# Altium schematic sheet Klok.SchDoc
size A4
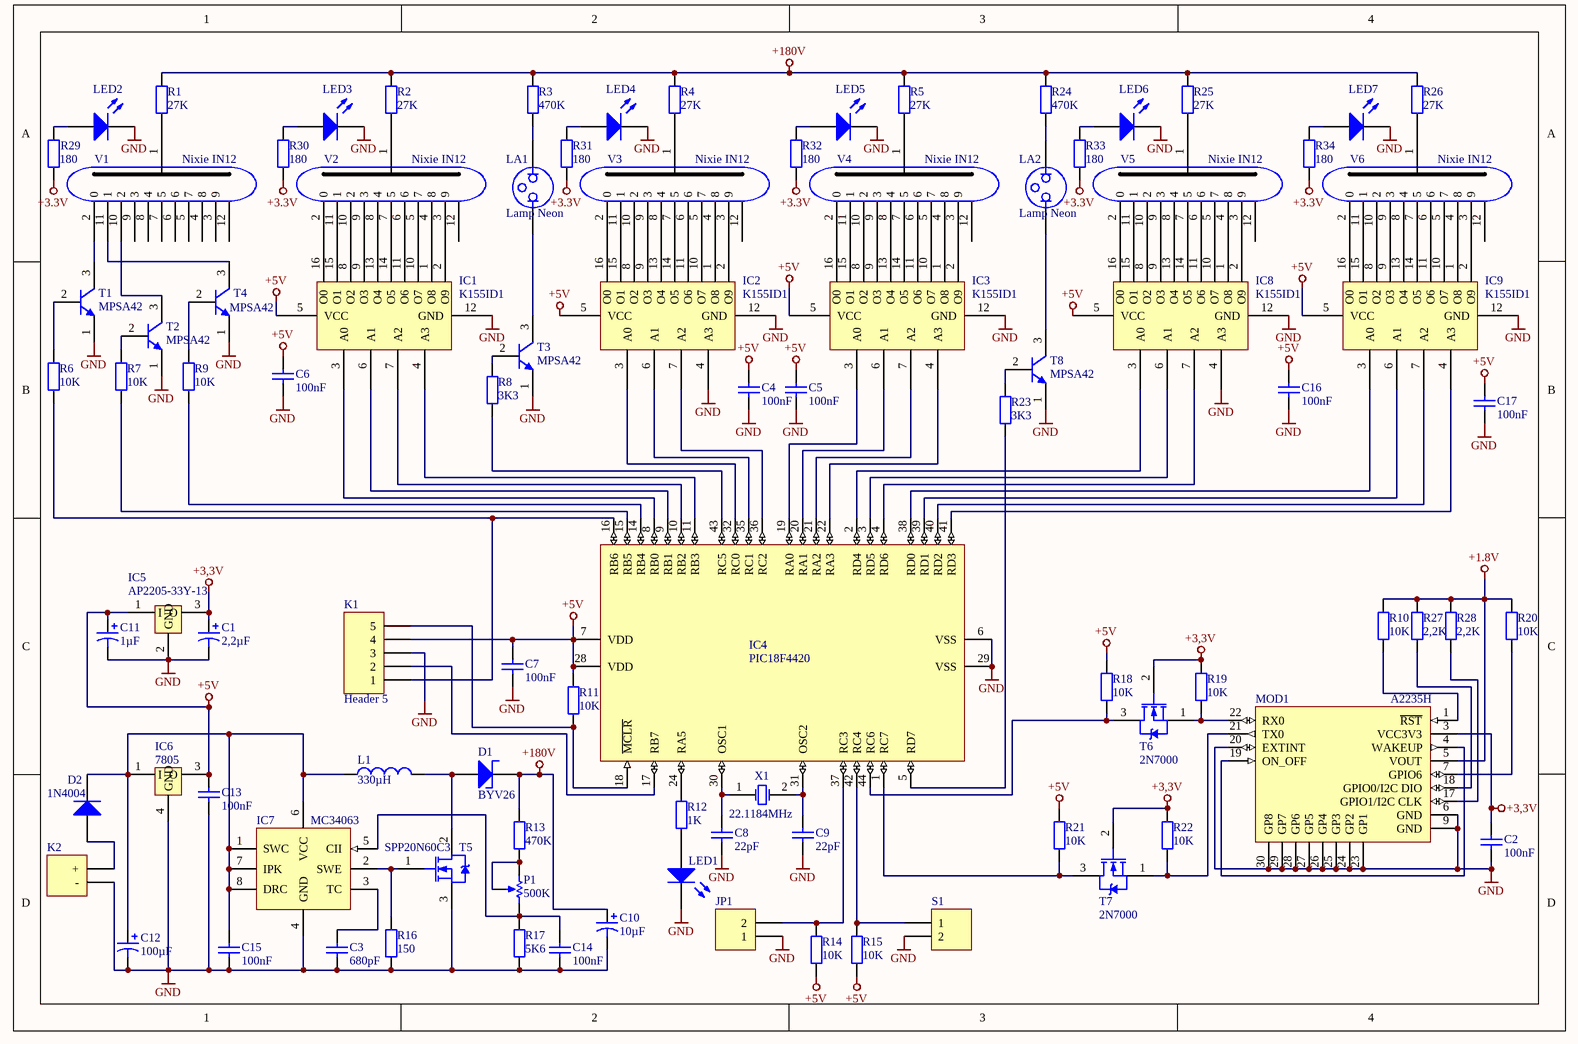
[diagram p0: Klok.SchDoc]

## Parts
C1  value 2,2µF  [ELCO2.2]  (hidden comment: Cap Pol1)
C2  value 100nF  [1206_Capacitor]  (hidden comment: Cap)
C3  value 680pF  [1206_Capacitor]  (hidden comment: Cap)
C4  value 100nF  [1206_Capacitor]  (hidden comment: Cap)
C5  value 100nF  [1206_Capacitor]  (hidden comment: Cap)
C6  value 100nF  [1206_Capacitor]  (hidden comment: Cap)
C7  value 100nF  [1206_Capacitor]  (hidden comment: Cap)
C8  value 22pF  [1206_Capacitor]  (hidden comment: Cap)
C9  value 22pF  [1206_Capacitor]  (hidden comment: Cap)
C10  value 10µF  [ELCO10]  (hidden comment: Cap Pol1)
C11  value 1µF  [ELCO100]  (hidden comment: Cap Pol1)
C12  value 100µF  [ELCO100]  (hidden comment: Cap Pol1)
C13  value 100nF  [1206_Capacitor]  (hidden comment: Cap)
C14  value 100nF  [1206_Capacitor]  (hidden comment: Cap)
C15  value 100nF  [1206_Capacitor]  (hidden comment: Cap)
C16  value 100nF  [1206_Capacitor]  (hidden comment: Cap)
C17  value 100nF  [1206_Capacitor]  (hidden comment: Cap)
D1  BYV26  [Through_Hole]
D2  1N4004  [DO-41]
IC1  K155ID1  [K155ID1]
IC2  K155ID1  [K155ID1]
IC3  K155ID1  [K155ID1]
IC4  PIC18F4420  [PIC18F4420]
IC5  AP2205-33Y-13  [AP2205-33Y-13]
IC6  7805  [7805]
IC7  MC34063  [MC34063]
IC8  K155ID1  [K155ID1]
IC9  K155ID1  [K155ID1]
JP1  Header 2  [HDR1X2]  (value not drawn)
K1  Header 5  [HDR1X5]
K2  Kroonsteen  [KROONSTEEN]  (value not drawn)
L1  value 330µH  [Inductor]  (hidden comment: Inductor)
LA1  Lamp Neon  [Neon_Lamp]
LA2  Lamp Neon  [Neon_Lamp]
LED1  LED0  [1206_LED]  (value not drawn)
LED2  LED0  [1206_LED]  (value not drawn)
LED3  LED0  [1206_LED]  (value not drawn)
LED4  LED0  [1206_LED]  (value not drawn)
LED5  LED0  [1206_LED]  (value not drawn)
LED6  LED0  [1206_LED]  (value not drawn)
LED7  LED0  [1206_LED]  (value not drawn)
MOD1  A2235H  [A2235H]
P1  value 500K  [Pot]  (hidden comment: RPot)
R1  value 27K  [1206_Resistor]  (hidden comment: Res2)
R2  value 27K  [1206_Resistor]  (hidden comment: Res2)
R3  value 470K  [1206_Resistor]  (hidden comment: Res2)
R4  value 27K  [1206_Resistor]  (hidden comment: Res2)
R5  value 27K  [1206_Resistor]  (hidden comment: Res2)
R6  value 10K  [1206_Resistor]  (hidden comment: Res2)
R7  value 10K  [1206_Resistor]  (hidden comment: Res2)
R8  value 3K3  [1206_Resistor]  (hidden comment: Res2)
R9  value 10K  [1206_Resistor]  (hidden comment: Res2)
R10  value 10K  [1206_Resistor]  (hidden comment: Res2)
R11  value 10K  [1206_Resistor]  (hidden comment: Res2)
R12  value 1K  [1206_Resistor]  (hidden comment: Res2)
R13  value 470K  [1206_Resistor]  (hidden comment: Res2)
R14  value 10K  [1206_Resistor]  (hidden comment: Res2)
R15  value 10K  [1206_Resistor]  (hidden comment: Res2)
R16  value 150  [1206_Resistor]  (hidden comment: Res2)
R17  value 5K6  [1206_Resistor]  (hidden comment: Res2)
R18  value 10K  [1206_Resistor]  (hidden comment: Res2)
R19  value 10K  [1206_Resistor]  (hidden comment: Res2)
R20  value 10K  [1206_Resistor]  (hidden comment: Res2)
R21  value 10K  [1206_Resistor]  (hidden comment: Res2)
R22  value 10K  [1206_Resistor]  (hidden comment: Res2)
R23  value 3K3  [1206_Resistor]  (hidden comment: Res2)
R24  value 470K  [1206_Resistor]  (hidden comment: Res2)
R25  value 27K  [1206_Resistor]  (hidden comment: Res2)
R26  value 27K  [1206_Resistor]  (hidden comment: Res2)
R27  value 2,2K  [1206_Resistor]  (hidden comment: Res2)
R28  value 2,2K  [1206_Resistor]  (hidden comment: Res2)
R29  value 180  [1206_Resistor]  (hidden comment: Res2)
R30  value 180  [1206_Resistor]  (hidden comment: Res2)
R31  value 180  [1206_Resistor]  (hidden comment: Res2)
R32  value 180  [1206_Resistor]  (hidden comment: Res2)
R33  value 180  [1206_Resistor]  (hidden comment: Res2)
R34  value 180  [1206_Resistor]  (hidden comment: Res2)
S1  Switch  [HDR1X2]  (value not drawn)
T1  MPSA42  [MPSA42]
T2  MPSA42  [MPSA42]
T3  MPSA42  [MPSA42]
T4  MPSA42  [MPSA42]
T5  SPP20N60C3  [SPP20N60C3]
T6  2N7000  [2N7000]
T7  2N7000  [2N7000]
T8  MPSA42  [MPSA42]
V1  Nixie IN12  [Nixie IN12]
V2  Nixie IN12  [Nixie IN12]
V3  Nixie IN12  [Nixie IN12]
V4  Nixie IN12  [Nixie IN12]
V5  Nixie IN12  [Nixie IN12]
V6  Nixie IN12  [Nixie IN12]
X1  22.1184MHz  [XTAL - duplicate]

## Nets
+1.8V: MOD1.5(VOUT) R10.2 R20.2 R27.2 R28.2
+3,3V: C1.1 C2.2 IC5.3(O) MOD1.3(VCC3V3) R19.2 R22.2 T6.2(G) T7.2(G)
+3.3V: R29.1 R30.1 R31.1 R32.1 R33.1 R34.1
+5V: C4.2 C5.2 C6.2 C7.2 C11.1 C13.2 C16.2 C17.2 IC1.5(VCC) IC2.5(VCC) IC3.5(VCC) IC4.7(VDD) IC4.28(VDD) IC5.1(I) IC6.3(O) IC8.5(VCC) IC9.5(VCC) K1.4 R11.2 R14.1 R15.1 R18.2 R21.2
+180V: C10.1 D1.2(K) R1.2 R2.2 R3.2 R4.2 R5.2 R13.2 R24.2 R25.2 R26.2
GND: C1.2 C2.1 C3.1 C4.1 C5.1 C6.1 C7.1 C8.1 C9.1 C10.2 C11.2 C12.2 C13.1 C14.1 C15.1 C16.1 C17.1 IC1.12(GND) IC2.4(A3) IC2.12(GND) IC3.12(GND) IC4.6(VSS) IC4.29(VSS) IC5.2(GND) IC6.4(GND) IC7.4(GND) IC8.4(A3) IC8.12(GND) IC9.12(GND) JP1.1 K1.3 K2.1(-) LED1.2(K) LED2.2(K) LED3.2(K) LED4.2(K) LED5.2(K) LED6.2(K) LED7.2(K) MOD1.6(GND) MOD1.9(GND) MOD1.20(EXTINT) MOD1.23(GP1) MOD1.24(GP2) MOD1.25(GP3) MOD1.26(GP4) MOD1.27(GP5) MOD1.28(GP6) MOD1.29(GP7) MOD1.30(GP8) R16.1 R17.1 S1.2 T1.1(E) T2.1(E) T3.1(E) T4.1(E) T5.3(SOURCE) T8.1(E)
NetC3_2: C3.2 IC7.3(TC)
NetC8_2: C8.2 IC4.30(OSC1) X1.1(OSC1)
NetC9_2: C9.2 IC4.31(OSC2) X1.2(OSC2)
NetC12_1: C12.1 C15.2 D2.2(K) IC6.1(I) IC7.1(SWC) IC7.6(VCC) IC7.7(IPK) IC7.8(DRC) L1.1
NetC14_2: C14.2 IC7.5(CII) P1.2(BOT) R17.2
NetD1_1: D1.1(A) L1.2 T5.2(DRAIN)
NetD2_1: D2.1(A) K2.2(+)
NetIC1_1: IC1.1(O8) V2.4(8)
NetIC1_2: IC1.2(O9) V2.3(9)
NetIC1_3: IC1.3(A0) IC4.8(RB0)
NetIC1_4: IC1.4(A3) IC4.11(RB3)
NetIC1_6: IC1.6(A1) IC4.9(RB1)
NetIC1_7: IC1.7(A2) IC4.10(RB2)
NetIC1_8: IC1.8(O2) V2.10(2)
NetIC1_9: IC1.9(O3) V2.9(3)
NetIC1_10: IC1.10(O7) V2.5(7)
NetIC1_11: IC1.11(O6) V2.6
NetIC1_13: IC1.13(O4) V2.8(4)
NetIC1_14: IC1.14(O5) V2.7(5)
NetIC1_15: IC1.15(O1) V2.11(1)
NetIC1_16: IC1.16(O0) V2.2(0)
NetIC2_1: IC2.1(O8) V3.4(8)
NetIC2_2: IC2.2(O9) V3.3(9)
NetIC2_3: IC2.3(A0) IC4.32(RC0)
NetIC2_6: IC2.6(A1) IC4.35(RC1)
NetIC2_7: IC2.7(A2) IC4.36(RC2)
NetIC2_8: IC2.8(O2) V3.10(2)
NetIC2_9: IC2.9(O3) V3.9(3)
NetIC2_10: IC2.10(O7) V3.5(7)
NetIC2_11: IC2.11(O6) V3.6
NetIC2_13: IC2.13(O4) V3.8(4)
NetIC2_14: IC2.14(O5) V3.7(5)
NetIC2_15: IC2.15(O1) V3.11(1)
NetIC2_16: IC2.16(O0) V3.2(0)
NetIC3_1: IC3.1(O8) V4.4(8)
NetIC3_2: IC3.2(O9) V4.3(9)
NetIC3_3: IC3.3(A0) IC4.19(RA0)
NetIC3_4: IC3.4(A3) IC4.22(RA3)
NetIC3_6: IC3.6(A1) IC4.20(RA1)
NetIC3_7: IC3.7(A2) IC4.21(RA2)
NetIC3_8: IC3.8(O2) V4.10(2)
NetIC3_9: IC3.9(O3) V4.9(3)
NetIC3_10: IC3.10(O7) V4.5(7)
NetIC3_11: IC3.11(O6) V4.6
NetIC3_13: IC3.13(O4) V4.8(4)
NetIC3_14: IC3.14(O5) V4.7(5)
NetIC3_15: IC3.15(O1) V4.11(1)
NetIC3_16: IC3.16(O0) V4.2(0)
NetIC4_1: IC4.1(RC7) R21.1 T7.3(D)
NetIC4_2: IC4.2(RD4) IC8.3(A0)
NetIC4_3: IC4.3(RD5) IC8.6(A1)
NetIC4_4: IC4.4(RD6) IC8.7(A2)
NetIC4_5: IC4.5(RD7) R23.1
NetIC4_14: IC4.14(RB4) R9.1
NetIC4_15: IC4.15(RB5) R7.1
NetIC4_16: IC4.16(RB6) K1.1 R6.1
NetIC4_17: IC4.17(RB7) K1.2
NetIC4_18: IC4.18(~{MCLR}) K1.5 R11.1
NetIC4_24: IC4.24(RA5) R12.2
NetIC4_37: IC4.37(RC3) JP1.2 R14.2
NetIC4_38: IC4.38(RD0) IC9.3(A0)
NetIC4_39: IC4.39(RD1) IC9.6(A1)
NetIC4_40: IC4.40(RD2) IC9.7(A2)
NetIC4_41: IC4.41(RD3) IC9.4(A3)
NetIC4_42: IC4.42(RC4) R15.2 S1.1
NetIC4_43: IC4.43(RC5) R8.1
NetIC4_44: IC4.44(RC6) R18.1 T6.3(D)
NetIC7_2: IC7.2(SWE) R16.2 T5.1(GATE)
NetIC8_1: IC8.1(O8) V5.4(8)
NetIC8_2: IC8.2(O9) V5.3(9)
NetIC8_8: IC8.8(O2) V5.10(2)
NetIC8_9: IC8.9(O3) V5.9(3)
NetIC8_10: IC8.10(O7) V5.5(7)
NetIC8_11: IC8.11(O6) V5.6
NetIC8_13: IC8.13(O4) V5.8(4)
NetIC8_14: IC8.14(O5) V5.7(5)
NetIC8_15: IC8.15(O1) V5.11(1)
NetIC8_16: IC8.16(O0) V5.2(0)
NetIC9_1: IC9.1(O8) V6.4(8)
NetIC9_2: IC9.2(O9) V6.3(9)
NetIC9_8: IC9.8(O2) V6.10(2)
NetIC9_9: IC9.9(O3) V6.9(3)
NetIC9_10: IC9.10(O7) V6.5(7)
NetIC9_11: IC9.11(O6) V6.6
NetIC9_13: IC9.13(O4) V6.8(4)
NetIC9_14: IC9.14(O5) V6.7(5)
NetIC9_15: IC9.15(O1) V6.11(1)
NetIC9_16: IC9.16(O0) V6.2(0)
NetLA1_1: LA1.1 T3.3(C)
NetLA1_2: LA1.2 R3.1
NetLA2_1: LA2.1 T8.3(C)
NetLA2_2: LA2.2 R24.1
NetLED1_1: LED1.1(A) R12.1
NetLED2_1: LED2.1(A) R29.2
NetLED3_1: LED3.1(A) R30.2
NetLED4_1: LED4.1(A) R31.2
NetLED5_1: LED5.1(A) R32.2
NetLED6_1: LED6.1(A) R33.2
NetLED7_1: LED7.1(A) R34.2
NetMOD1_1: MOD1.1(~{RST}) R10.1
NetMOD1_4: MOD1.4(WAKEUP) MOD1.19(ON_OFF)
NetMOD1_7: MOD1.7(GPIO6) R20.1
NetMOD1_17: MOD1.17(GPIO1/I2C_CLK) R28.1
NetMOD1_18: MOD1.18(GPIO0/I2C_DIO) R27.1
NetMOD1_21: MOD1.21(TX0) R22.1 T7.1(S)
NetMOD1_22: MOD1.22(RX0) R19.1 T6.1(S)
NetP1_1: P1.1(TOP) P1.3(TAP) R13.1
NetR1_1: R1.1 V1.1
NetR2_1: R2.1 V2.1
NetR4_1: R4.1 V3.1
NetR5_1: R5.1 V4.1
NetR6_2: R6.2 T1.2(B)
NetR7_2: R7.2 T2.2(B)
NetR8_2: R8.2 T3.2(B)
NetR9_2: R9.2 T4.2(B)
NetR23_2: R23.2 T8.2(B)
NetR25_1: R25.1 V5.1
NetR26_1: R26.1 V6.1
NetT1_3: T1.3(C) V1.2(0)
NetT2_3: T2.3(C) V1.10(2)
NetT4_3: T4.3(C) V1.11(1)

Not connected (* = marked no-connect by the designer): V1 3(9) 4(8) 5(7) 6 7(5) 8(4) 9(3) 12(25); V2 12(25); V3 12(25); V4 12(25); V5 12(25); V6 12(25)

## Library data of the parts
C1 C10-C12 = Cap Pol1: Polarized Capacitor (Radial)
C2-C9 C13-C17 = Cap: Capacitor
D2 = Diode 1N4004: 1 Amp General Purpose Rectifier
JP1 K2 S1 = Header 2: Header, 2-Pin
K1 = Header 5: Header, 5-Pin
L1 = Inductor: Code_IEC: 1005
LA1 LA2 = Lamp Neon: Neon Lamp
LED1-LED7 = LED0: Typical INFRARED GaAs LED
P1 = RPot: Potentiometer; Sim Note: Enter the Resistance value and the set point into parameter fields.; Set Position: 0.5
R1-R34 = Res2: Resistor
X1 = XTAL: Crystal Oscillator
